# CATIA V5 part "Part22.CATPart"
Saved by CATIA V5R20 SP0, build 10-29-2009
Part number: 9TS2008M8
Revision: ANY
Definition: UNKNOWN
Nomenclature: 9TS2008M8
Source: Unknown
Bounding box of the stored display mesh (mm): x -10 to 10, y -10 to 10, z 0 to 8
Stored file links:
  C:\Users\Utente\Desktop\IO LAVORO\3D X SITO CF\CUMSA\3D files GR\GR 344038-10\Part22.CATPart
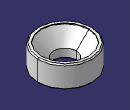
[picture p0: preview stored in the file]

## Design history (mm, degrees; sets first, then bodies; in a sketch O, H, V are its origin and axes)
Body1 "Chaflán1" (main body)
  Solid1: solid without history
